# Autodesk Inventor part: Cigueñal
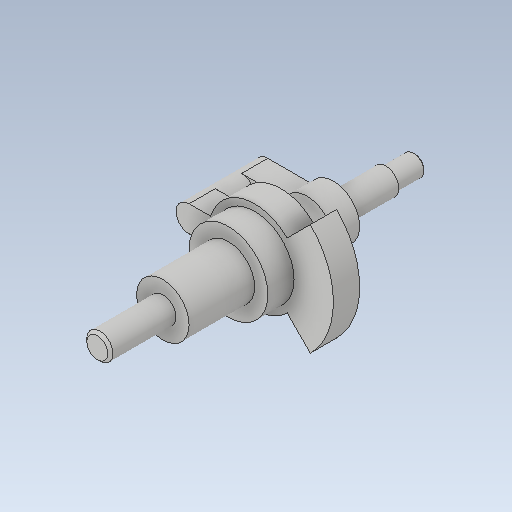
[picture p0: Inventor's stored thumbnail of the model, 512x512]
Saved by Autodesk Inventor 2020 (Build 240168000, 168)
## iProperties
Created: 2019-09
Part Number: Cigueñal
Material: Generic
Document SubType Name: Modeling
Designer: user
Density: 1 g/cm^3
Appearance: Default
Author: user
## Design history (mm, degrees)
sketch "Sketch1"
  geometry: C1 r 5 at (0, 0); 1 further point
  constraints: 1 centre point, 1 coincident
  dimensions: "d0" = 10 diameter of C1
extrude "Extrusion1" new body sketch "Sketch1" distance "d1" = 25; taper "d2" = 0 deg
chamfer "Chamfer1" distance "d3" = 1; stored, may be unused: second distance "d4" = 2, angle "d5" = 45 deg
sketch "Sketch2"
  geometry: C1 r 10 at (0, 0); 1 further point
  constraints: 1 centre point, 1 coincident
  dimensions: "d6" = 20 diameter of C1
extrude "Extrusion2" join sketch "Sketch2" distance "d7" = 25; taper "d8" = 0 deg
sketch "Sketch3"
  geometry: C1 r 15 at (0, 0); 1 further point
  constraints: 1 centre point, 1 coincident
  dimensions: "d9" = 30 diameter of C1
extrude "Extrusion3" join sketch "Sketch3" distance "d10" = 10; taper "d11" = 0 deg
sketch "Sketch4"
  geometry: L1 (25, 5)-(16.771, 5); L2 (25, -5)-(16.771, -5); L3 (-12.374, -12.374)-(-21.213, -21.213); L4 (0, 0)-(30, 0); L5 (-12.374, 12.374)-(-21.213, 21.213); A1 r 5 centre (25, 0) between (25, -5) and (25, 5); A2 r 30 centre (0, 0) between (-21.213, 21.213) and (-21.213, -21.213); A3 r 17.5 centre (0, 0) between (16.771, 5) and (-12.374, 12.374); A4 r 17.5 centre (0, 0) between (-12.374, -12.374) and (16.771, -5); 1 further point
  constraints: 10 end point, 8 point on circle, 4 centre point, 2 coincident, 2 horizontal, 1 parallel, 1 tangent
  dimensions: "d13" = 10 diameter of A1; "d14" = 25 distance of point (0, 0) A1.centre; "d15" = 135 deg angle of L3 L4
extrude "Extrusion4" join sketch "Sketch4" distance "d16" = 10; taper "d17" = 0 deg
sketch "Sketch5"
  geometry: C1 r 5 at (25, 0); A1 r 5 centre (25, 0) between (25, -5) and (25, 5) reference; 1 further point
  constraints: 1 centre point, 1 coincident
extrude "Extrusion5" join sketch "Sketch5" distance "d18" = 10; taper "d19" = 0 deg
sketch "Sketch6"
  geometry: L1 (0, 5)-(-16.34, 5); L2 (0, -5)-(-16.34, -5); L3 (-8.229, -5)-(0, -5) reference; A1 r 5 centre (0, 0) between (0, -5) and (0, 5); A2 r 10 centre (-25, 0) between (-16.34, 5) and (-16.34, -5); 1 further point
  constraints: 5 end point, 4 point on circle, 2 centre point, 1 coincident, 1 collinear, 1 horizontal
extrude "Extrusion6" join sketch "Sketch6" distance "d20" = 10; taper "d21" = 0 deg
sketch "Sketch7"
  geometry: C1 r 5 at (-25, 0); 1 further point
  constraints: 1 centre point, 1 coincident
extrude "Extrusion7" join sketch "Sketch7" distance "d22" = 20; taper "d23" = 0 deg
sketch "Sketch8"
  geometry: C1 r 5 at (0, 0) reference; C2 r 4 at (0, 0); 1 further point
  constraints: 1 centre point, 1 coincident
  dimensions: "d24" = 8 diameter of C2
extrude "Extrusion8" join sketch "Sketch8" distance "d25" = 11; taper "d26" = 0 deg
chamfer "Chamfer2" distance "d27" = 0.5; stored, may be unused: second distance "d28" = 2, angle "d29" = 45 deg
body "Solid1"
other parameters: "d12" = 35
